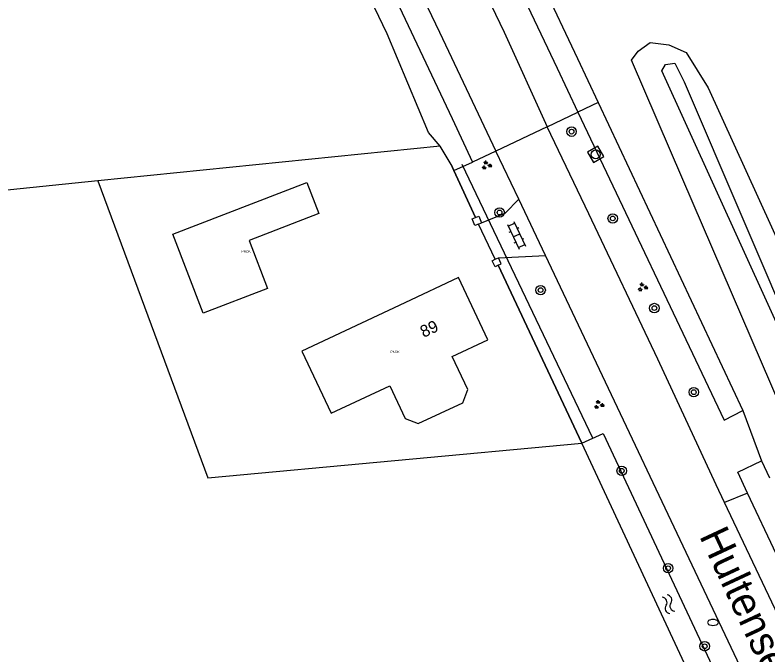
# Model space of a CAD drawing. Extents: x 125000 to 129004, y 397500 to 399008.
# Drawn here: x 125798.5 to 125861.8, y 397697.6 to 397751.4 of the extents above; entities that cross this region are included whole.
import ezdxf

# ---------------------------------------------------------------- set-up
doc = ezdxf.new("R2010")
doc.units = 0
for name, color, linetype in [('gg-afsc-hekwerk', 7, 'Continuous'), ('gg-anno-huisnummerreeks BGT', 7, 'Continuous'), ('gg-anno-openbare ruimte label', 7, 'Continuous'), ('gg-knt-verharding', 7, 'Continuous'), ('gg-kntw-beschoeiing', 7, 'Continuous'), ('gg-kntw-bovenkant insteek waterloop', 7, 'Continuous'), ('gg-kwrk-duiker nz buis', 7, 'Continuous'), ('gt-grn-groengrens', 7, 'Continuous'), ('gt-grn-vlakafsluiter', 7, 'Continuous'), ('gt-symb-boom', 7, 'Continuous'), ('gt-symb-brandkraan', 7, 'Continuous'), ('gt-symb-groenvak', 7, 'Continuous'), ('gt-symb-klinker verharding', 7, 'Continuous'), ('gt-symb-rioolschacht', 7, 'Continuous'), ('gt-symb-watersymbool', 7, 'Continuous'), ('gx-grn-maaiveld', 7, 'Continuous'), ('kenmerkpunt-x pandkandidaat', 7, 'Continuous')]:
    doc.layers.add(name, color=color, linetype=linetype)

# ---------------------------------------------------------------- blocks, each defined once
blk = doc.blocks.new('gt0-RS')
at = {"layer": 'gt-symb-rioolschacht'}
blk.add_lwpolyline([(-0.5, -0.5), (0.5, -0.5), (0.5, 0.5), (-0.5, 0.5)], close=True, dxfattribs=at)
blk.add_circle((0, 0), 0.375, dxfattribs=at)
blk = doc.blocks.new('gt0-BOOM')
at = {"layer": 'gt-symb-boom'}
for radius in [0.4, 0.2]:
    blk.add_circle((0, 0), radius, dxfattribs=at)
blk = doc.blocks.new('gt0-KL1')
at = {"layer": 'gt-symb-klinker verharding'}
for p, q in [((-1.15, 0.3), (1.15, 0.3)), ((-1, -0.3), (-1, 0.3)), ((-0.5, 0.3), (-0.5, 0.45)), ((0, -0.3), (0, 0.3)), ((0.5, 0.3), (0.5, 0.45)), ((1, -0.3), (1, 0.3)), ((-1.15, -0.3), (1.15, -0.3)), ((-0.5, -0.45), (-0.5, -0.3)), ((0.5, -0.45), (0.5, -0.3))]:
    blk.add_line(p, q, dxfattribs=at)
blk = doc.blocks.new('gt0-GRVAK')
at = {"layer": 'gt-symb-groenvak'}
for p, q in [((-0.11, 0.189), (-0.228, 0.24)), ((-0.182, 0.153), (0.088, 0.153)), ((-0.091, 0.211), (-0.156, 0.322)), ((-0.047, 0.214), (-0.047, 0.393)), ((-0.004, 0.211), (0.061, 0.322)), ((0.015, 0.189), (0.133, 0.24)), ((0.262, -0.052), (0.197, 0.059)), ((0.305, -0.049), (0.305, 0.13)), ((0.349, -0.052), (0.414, 0.059)), ((-0.245, -0.228), (-0.363, -0.177)), ((-0.318, -0.264), (-0.047, -0.264)), ((-0.226, -0.206), (-0.291, -0.095)), ((-0.183, -0.203), (-0.183, -0.024)), ((-0.139, -0.206), (-0.074, -0.095)), ((-0.12, -0.228), (-0.002, -0.177)), ((0.243, -0.074), (0.125, -0.023)), ((0.17, -0.11), (0.441, -0.11)), ((0.368, -0.074), (0.486, -0.023))]:
    blk.add_line(p, q, dxfattribs=at)
blk = doc.blocks.new('gt0-BR')
at = {"layer": 'gt-symb-brandkraan'}
for centre, radius, start, end in [((-0.244, 0), 0.206, 107.56694, 252.43307), ((0.599, -2.664), 3, 106.89205, 107.56694), ((0, -0.691), 0.938, 73.10799, 106.89205), ((-0.599, -2.664), 3, 72.43309, 73.10799), ((0.244, 0), 0.206, 287.56695, 72.43309), ((0.599, 2.664), 3, 252.43307, 253.10797), ((0, 0.691), 0.938, 253.10797, 286.89206), ((-0.599, 2.664), 3, 286.89206, 287.56695)]:
    blk.add_arc(centre, radius, start, end, dxfattribs=at)
blk = doc.blocks.new('gt0-WA')
at = {"layer": 'gt-symb-watersymbool'}
for centre, start, end in [((-0.323, 0.022), 28.07249, 151.92751), ((0.427, 0.422), 208.07248, 331.92751), ((-0.323, -0.428), 28.07249, 151.92751), ((0.427, -0.028), 208.07248, 331.92751)]:
    blk.add_arc(centre, 0.425, start, end, dxfattribs=at)

msp = doc.modelspace()

# ---------------------------------------------------------------- linework, layer by layer
at = {"layer": 'gg-afsc-hekwerk'}
msp.add_line((125859.123, 397687.662), (125846.176, 397715.436), dxfattribs=at)
msp.add_line((125859.123, 397687.662), (125846.176, 397715.436), dxfattribs=at)
at = {"layer": 'gg-knt-verharding'}
for p, q in [((125840.858, 397735.961), (125838.937, 397740)), ((125843.117, 397731.212), (125840.858, 397735.961)), ((125839.143, 397731.023), (125843.117, 397731.212)), ((125860.868, 397693.768), (125843.117, 397731.212))]:
    msp.add_line(p, q, dxfattribs=at)
for points in [[(125858.18, 397710.44), (125857.479, 397711.915), (125852.567, 397722.494), (125846.767, 397734.715), (125843.243, 397742.053)], [(125837.729, 397733.979), (125839.706, 397734.795), (125840.858, 397735.961)], [(125863.939, 397698.333), (125863.762, 397698.695), (125858.18, 397710.44)]]:
    msp.add_lwpolyline(points, dxfattribs=at)
at = {"layer": 'gg-kntw-beschoeiing'}
for p, q in [((125835.17, 397738.874), (125835.394, 397738.384)), ((125835.394, 397738.384), (125837.211, 397734.42)), ((125839.122, 397730.397), (125846.176, 397715.436))]:
    msp.add_line(p, q, dxfattribs=at)
at = {"layer": 'gg-kntw-bovenkant insteek waterloop'}
msp.add_line((125861.303, 397713.933), (125861.974, 397712.517), dxfattribs=at)
for points in [[(125845.839, 397743.291), (125858.154, 397717.373), (125859.723, 397718.174)], [(125846.176, 397715.436), (125847.951, 397716.244), (125860.989, 397688.504), (125859.123, 397687.662)], [(125860.124, 397711.22), (125859.29, 397712.979), (125861.303, 397713.933)], [(125867.025, 397701.862), (125865.012, 397700.907), (125860.124, 397711.22)]]:
    msp.add_lwpolyline(points, dxfattribs=at)
at = {"layer": 'gg-kwrk-duiker nz buis'}
msp.add_line((125847.095, 397715.864), (125836.104, 397738.866), dxfattribs=at)
at = {"layer": 'gt-grn-groengrens'}
msp.add_line((125860.124, 397711.22), (125858.18, 397710.44), dxfattribs=at)
at = {"layer": 'gt-grn-vlakafsluiter'}
msp.add_line((125859.723, 397718.174), (125861.303, 397713.933), dxfattribs=at)
at = {"layer": 'gx-grn-maaiveld'}
for p, q in [((125847.534, 397744.099), (125845.839, 397743.291)), ((125847.534, 397744.099), (125859.723, 397718.174)), ((125843.243, 397742.053), (125845.839, 397743.291)), ((125843.243, 397742.053), (125838.937, 397740)), ((125834.251, 397740.431), (125805.416, 397737.49)), ((125838.937, 397740), (125836.976, 397739.068)), ((125835.394, 397738.384), (125836.976, 397739.068)), ((125837.211, 397734.42), (125835.394, 397738.384)), ((125805.416, 397737.49), (125750.706, 397731.911)), ((125837.466, 397733.864), (125837.729, 397733.979)), ((125838.881, 397730.901), (125837.466, 397733.864)), ((125838.881, 397730.901), (125839.143, 397731.023)), ((125846.176, 397715.436), (125839.122, 397730.397))]:
    msp.add_line(p, q, dxfattribs=at)
for points in [[(125800.11, 397813.996), (125801.269, 397814.53), (125819.18, 397776.729), (125835.243, 397742.734), (125836.976, 397739.068)], [(125834.251, 397740.431), (125833.272, 397741.565), (125829.791, 397749.872), (125817.309, 397775.776), (125799.236, 397813.593)], [(125810.221, 397799.898), (125834.18, 397750), (125838.937, 397740)], [(125830.308, 397780.74), (125842.811, 397754.146), (125845.799, 397747.789), (125847.534, 397744.099)], [(125828.368, 397780.061), (125841.051, 397753.369), (125844.091, 397746.971), (125845.839, 397743.291)], [(125825.775, 397778.814), (125839.635, 397750), (125843.243, 397742.053)], [(125862.945, 397718.409), (125854.67, 397737.606), (125850.341, 397747.666), (125850.921, 397748.422), (125851.922, 397749.134), (125853.5, 397748.947), (125854.955, 397748.294), (125856.813, 397745.333), (125865.308, 397726.667)], [(125864.14, 397722.119), (125852.909, 397746.741), (125853.2, 397747.294), (125853.999, 397747.405), (125854.784, 397745.823), (125864.586, 397722.978)], [(125835.394, 397738.384), (125835.17, 397738.874), (125834.251, 397740.431)], [(125805.416, 397737.49), (125814.687, 397712.519), (125846.176, 397715.436)], [(125814.296, 397726.363), (125811.73, 397733.012), (125823.029, 397737.373), (125824.038, 397734.757), (125818.153, 397732.486), (125819.71, 397728.452), (125814.296, 397726.363)], [(125837.466, 397733.864), (125837.172, 397733.736), (125836.927, 397734.297), (125837.211, 397734.42)], [(125837.211, 397734.42), (125837.484, 397734.54), (125837.729, 397733.979)], [(125839.122, 397730.397), (125838.866, 397730.278), (125838.63, 397730.784), (125838.881, 397730.901)], [(125839.122, 397730.397), (125839.378, 397730.516), (125839.143, 397731.023)], [(125835.79, 397729.37), (125831.27, 397727.25), (125822.601, 397723.184), (125825.072, 397717.942), (125830.014, 397720.264), (125831.293, 397717.496), (125832.381, 397717.075), (125836.159, 397718.83), (125836.569, 397719.945), (125835.26, 397722.726), (125838.26, 397724.13), (125835.79, 397729.37)]]:
    msp.add_lwpolyline(points, dxfattribs=at)

# ---------------------------------------------------------------- block references
at = {"layer": 'gt-symb-boom'}
for p in [(125845.302, 397741.641), (125839.244, 397734.837), (125848.769, 397734.335), (125842.698, 397728.306), (125852.274, 397726.799), (125855.593, 397719.723), (125849.526, 397713.104), (125853.43, 397704.912), (125856.509, 397698.346)]:
    msp.add_blockref('gt0-BOOM', p, dxfattribs=at)
at = {"layer": 'gt-symb-brandkraan'}
msp.add_blockref('gt0-BR', (125857.211, 397700.349), dxfattribs=at)
at = {"layer": 'gt-symb-groenvak'}
for p in [(125838.139, 397738.808), (125851.278, 397728.553), (125847.596, 397718.659)]:
    msp.add_blockref('gt0-GRVAK', p, dxfattribs=at)
at = {"layer": 'gt-symb-klinker verharding', "rotation": -64.53665493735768}
msp.add_blockref('gt0-KL1', (125840.667, 397732.918), dxfattribs=at)
at = {"layer": 'gt-symb-rioolschacht', "rotation": 119.5387822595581}
msp.add_blockref('gt0-RS', (125847.339, 397739.724), dxfattribs=at)
at = {"layer": 'gt-symb-watersymbool', "rotation": -64.71651982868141}
msp.add_blockref('gt0-WA', (125853.441, 397701.935), dxfattribs=at)

# ---------------------------------------------------------------- texts
at = {"layer": 'gg-anno-huisnummerreeks BGT'}
msp.add_text('89', height=1, rotation=25.2, dxfattribs=at).set_placement((125832.85, 397724.287))
at = {"layer": 'gg-anno-openbare ruimte label'}
msp.add_text('Hultenseweg', height=2.5, rotation=295, dxfattribs=at).set_placement((125856.021, 397707.634))
at = {"layer": 'kenmerkpunt-x pandkandidaat'}
for p in [(125817.513, 397731.467), (125830.06, 397723.009)]:
    msp.add_text('PNDK', height=0.2, dxfattribs=at).set_placement(p)

doc.saveas('drawing.dxf')
